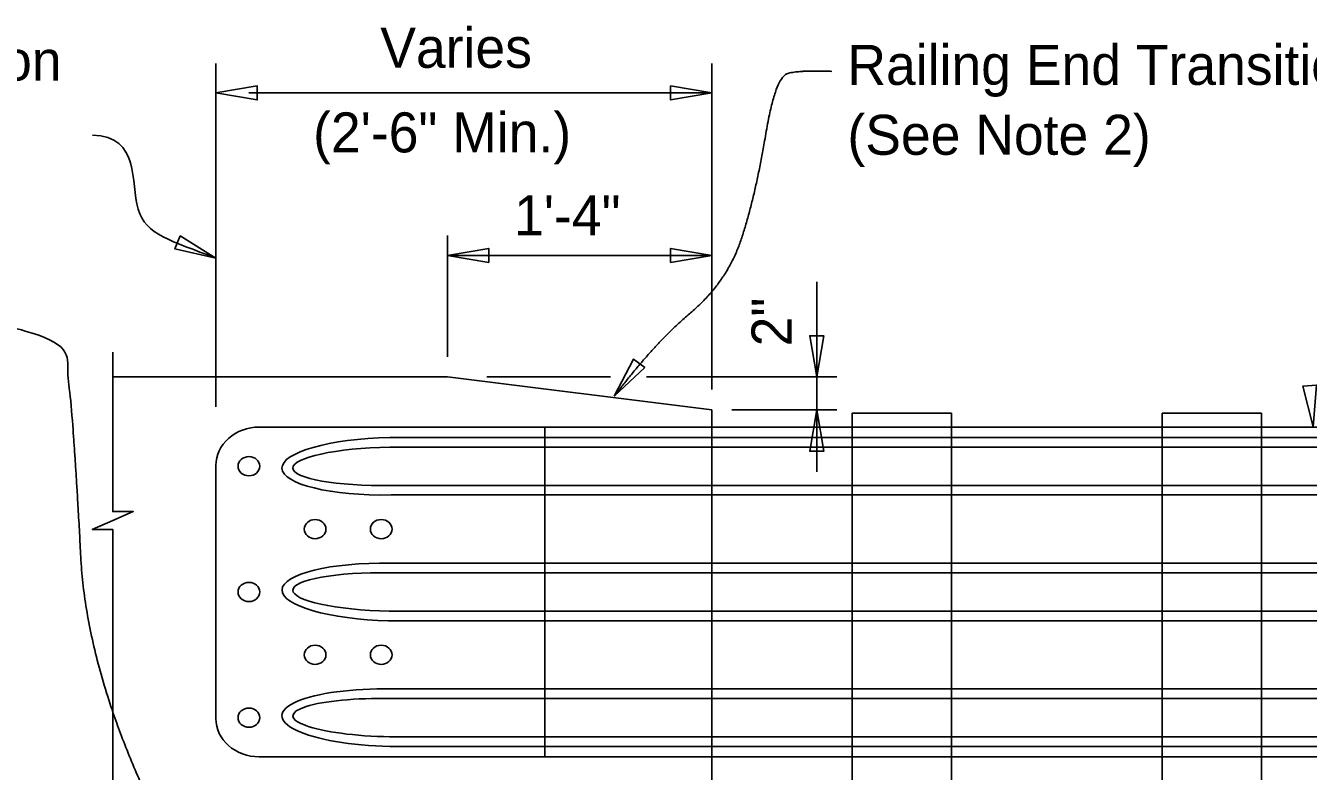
# Model space of a CAD drawing. Extents: x 1 to 39.2, y 0 to 26.
# Drawn here: x 26.61 to 33.07, y 11.73 to 15.48 of the extents above; entities that cross this region are included whole.
import ezdxf

# ---------------------------------------------------------------- set-up
doc = ezdxf.new("R2010")
doc.units = 0
for name, color, linetype in [('Dimension', 7, 'Continuous'), ('Miscellaneous', 7, 'Continuous'), ('SteelMisc_h', 7, 'Continuous'), ('TextStructures', 7, 'Continuous'), ('TrafBarrierConc', 7, 'Continuous')]:
    doc.layers.add(name, color=color, linetype=linetype)

# ---------------------------------------------------------------- blocks, each defined once
blk = doc.blocks.new('Terminator-Arrow')
at = {"layer": 'Dimension'}
blk.add_lwpolyline([(0, 0), (-0.00041, 0.000069), (-0.00041, -0.000069)], close=True, dxfattribs=at)

msp = doc.modelspace()

# ---------------------------------------------------------------- linework, layer by layer
at = {"layer": 'Dimension'}
for p, q in [((27.5656, 13.5648), (27.5656, 15.2946)), ((30.0656, 13.6526), (30.0656, 15.2946)), ((30.0656, 15.1463), (27.7323, 15.1463)), ((28.7323, 13.8171), (28.7323, 14.4286)), ((28.7323, 14.3278), (30.0656, 14.3278)), ((30.594, 14.1947), (30.594, 13.2386)), ((28.9316, 13.7163), (29.5543, 13.7163)), ((29.736, 13.7163), (30.6948, 13.7163)), ((30.1664, 13.5496), (30.6948, 13.5496))]:
    msp.add_line(p, q, dxfattribs=at)
for points in [[(27.5656, 15.1463), (27.7739, 15.111), (27.7739, 15.1816)], [(30.0656, 15.1463), (29.8574, 15.1816), (29.8574, 15.111)], [(27.5656, 14.3143), (27.3862, 14.4258), (27.3595, 14.3605)], [(28.7324, 14.3278), (28.9406, 14.2925), (28.9406, 14.3631)], [(30.0656, 14.3278), (29.8574, 14.3631), (29.8574, 14.2925)], [(29.5738, 13.6185), (29.7275, 13.7634), (29.6712, 13.8059)], [(33.0961, 13.4646), (33.1136, 13.6751), (33.0433, 13.6691)]]:
    msp.add_lwpolyline(points, close=True, dxfattribs=at)
for points in [[(27.0456, 12.0956), (27.0456, 12.9481), (26.9423, 12.9481), (27.0456, 12.9931), (27.1489, 13.0381), (27.0456, 13.0381), (27.0456, 13.8413)], [(27.0456, 8.9032), (27.0456, 11.0262), (26.9423, 11.0262), (27.0456, 11.0712), (27.1489, 11.1162), (27.0456, 11.1162), (27.0456, 12.0956)]]:
    msp.add_lwpolyline(points, dxfattribs=at)
for points, degree in [([(30.6702, 15.2547), (30.5145, 15.2612), (30.3847, 15.2287), (30.2874, 14.6379), (30.1447, 14.1963), (29.7749, 13.8847), (29.5738, 13.6185)], 2), ([(26.943, 14.9327), (27.186, 14.9288), (27.0846, 14.4569), (27.3401, 14.4028), (27.5656, 14.3143)], 3), ([(23.597, 14.1414), (26.7719, 14.1063), (26.8471, 13.5421), (26.9223, 12.0783), (27.4612, 11.1317)], 2)]:
    msp.add_open_spline(points, degree=degree, dxfattribs=at)
at = {"layer": 'Miscellaneous'}
for p, q in [((27.784, 13.463), (34.9557, 13.463)), ((29.2235, 11.8029), (29.2235, 13.463)), ((28.4416, 13.4108), (34.9557, 13.4108)), ((28.4429, 13.3626), (34.9557, 13.3626)), ((27.5656, 11.9957), (27.5656, 13.2702)), ((28.4476, 13.1698), (34.9557, 13.1698)), ((28.4487, 13.1215), (34.9557, 13.1215)), ((28.4453, 12.7776), (34.9557, 12.7776)), ((28.444, 12.7293), (34.9557, 12.7293)), ((28.4346, 12.4884), (34.9557, 12.4884)), ((28.4388, 12.5365), (34.9557, 12.5365)), ((28.4476, 12.0962), (34.9557, 12.0962)), ((28.4487, 12.1444), (34.9557, 12.1444)), ((28.4413, 11.9034), (34.9557, 11.9034)), ((28.4423, 11.8552), (34.9557, 11.8552)), ((27.784, 11.8029), (34.9557, 11.8029))]:
    msp.add_line(p, q, dxfattribs=at)
for points in [[(31.2725, 9.8041), (31.2725, 13.5329), (30.7725, 13.5329), (30.7725, 9.8041)], [(32.835, 9.8041), (32.835, 13.5329), (32.335, 13.5329), (32.335, 9.8041)]]:
    msp.add_lwpolyline(points, dxfattribs=at)
for centre, major_axis, ratio, start_param, end_param in [((27.7842, 13.2702), (0.2185, 0), 0.882613, 1.570796, 3.141593), ((28.4453, 13.2662), (-0.5464, -0.0102), 0.264749, 4.713933, 7.855525), ((28.4453, 13.2662), (-0.4917, -0.0093), 0.196063, 4.713495, 7.855087), ((28.4418, 12.6329), (-0.5428, 0.0103), 0.266477, 4.71081, 7.852402), ((28.4418, 12.6329), (-0.4882, 0.0094), 0.197486, 4.711258, 7.85285), ((28.4453, 11.9998), (-0.5464, 0.0102), 0.264749, 4.710845, 7.852438), ((28.4453, 11.9998), (-0.4917, 0.0093), 0.196063, 4.711283, 7.852876), ((27.7842, 11.9957), (0.2185, 0), 0.882613, 3.141593, 4.712389)]:
    msp.add_ellipse(centre, major_axis=major_axis, ratio=ratio, start_param=start_param, end_param=end_param, dxfattribs=at)
at = {"layer": 'SteelMisc_h'}
for centre in [(27.7323, 13.2661), (28.0656, 12.9495), (28.399, 12.9496), (27.7323, 12.633), (28.0656, 12.3165), (28.399, 12.3164), (27.7323, 11.9998)]:
    msp.add_ellipse(centre, major_axis=(0.0547, 0), ratio=0.882613, dxfattribs=at)
at = {"layer": 'TrafBarrierConc'}
for p, q in [((28.7323, 13.7163), (27.0456, 13.7163)), ((28.7323, 13.7163), (30.0656, 13.5496)), ((30.0656, 13.5496), (30.0656, 10.883))]:
    msp.add_line(p, q, dxfattribs=at)

# ---------------------------------------------------------------- block references
at = {"layer": 'Dimension', "xscale": 506.349, "yscale": 512.1577380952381}
for p, rotation in [((30.5937, 13.7161), -90), ((30.5937, 13.5494), 90)]:
    msp.add_blockref('Terminator-Arrow', p, dxfattribs=dict(at, rotation=rotation))

# ---------------------------------------------------------------- texts
at = {"layer": 'Dimension'}
for s, p in [('Limiting Station', (24.9447, 15.2083)), ('Railing End Transition ', (30.7487, 15.1866)), ('(See Note 2)', (30.7487, 14.8346))]:
    msp.add_text(s, height=0.2016, dxfattribs=at).set_placement(p)
at = {"layer": 'TextStructures'}
for s, p in [('Varies', (28.3944, 15.2726)), ('(2\'-6" Min.)', (28.0557, 14.8465)), ('1\'-4"', (29.0686, 14.4284))]:
    msp.add_text(s, height=0.2016, dxfattribs=at).set_placement(p)
msp.add_text('2"', height=0.2016, rotation=90, dxfattribs=at).set_placement((30.4669, 13.8696))

doc.saveas('drawing.dxf')
